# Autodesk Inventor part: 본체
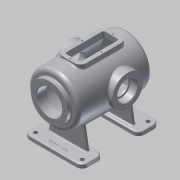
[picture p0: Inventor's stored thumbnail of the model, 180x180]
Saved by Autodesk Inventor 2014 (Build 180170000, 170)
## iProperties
Created: 2016-02
Part Number: 본체
Material: 알루미늄 6061
Document SubType Name: Modeling
Designer: mduedu
Density: 2.71 g/cm^3
Appearance: 알루미늄 - 평지
Mass: 3305.63 g
Surface Area: 2487.05 cm^2
Volume: 1219.79 cm^3
Author: mduedu
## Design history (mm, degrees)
sketch "스케치2"
  geometry: L1 (0, 100)-(0, -100); L2 (65, -87.083)-(65, 100); L3 (65, 100)-(0, 100); A1 r 170 centre (0, 70) between (0, -100) and (65, -87.083); 2 further points
  constraints: 6 end point, 2 point on circle, 1 centre point, 1 coincident, 1 horizontal, 1 midpoint, 1 parallel, 1 point on line, 1 vertical
  dimensions: "d3" = 200 distance of L1.start L1.end; "d5" = 130 diameter of L2 L1; "d6" = 170 radius of A1
revolve "회전1" sketch "스케치2" stored, may be unused: angle "d7" = 90 deg
sketch "스케치3"
  geometry: C1 r 47.5 at (0, 0); 1 further point
  constraints: 1 centre point, 1 coincident
  dimensions: "d8" = 95 diameter of C1
extrude "돌출2" join sketch "스케치3" distance "d10" = 10; taper "d11" = 0 deg
sketch "스케치5"
  geometry: L1 (47.5, 110)-(47.5, 100) reference; L2 (47.5, 100)-(65, 100) reference; L3 (65, 100)-(65, -87.083) reference; L4 (-65, -87.083)-(-65, 100) reference; L5 (-65, 100)-(-47.5, 100) reference; L6 (-47.5, 100)-(-47.5, 110) reference; L7 (-47.5, 110)-(47.5, 110) reference; L8 (55, 85)-(55, -80.25); L9 (0, 85)-(55, 85); L10 (0, 85)-(0, -90); A1 r 170 centre (0, 70) between (-65, -87.083) and (0, -100) reference; A2 r 170 centre (0, 70) between (0, -100) and (65, -87.083) reference; A3 r 160 centre (0, 70) between (0, -90) and (55, -80.25); 1 further point
  constraints: 6 end point, 2 point on circle, 1 centre point, 1 parallel, 1 perpendicular, 1 point on line, 1 vertical
  dimensions: "d13" = 10 distance between parallel lines of L3 L8; "d14" = 10 radial gap between concentric circles of A3 A1; "d15" = 15 distance between parallel lines of L9 L2
revolve "회전2" sketch "스케치5" stored, may be unused: angle "d16" = 90 deg
hole "구멍1" diameter "d19" = 65; stored, may be unused: countersink angle "d23" = 90 deg, drill point angle "d25" = 118 deg; dims "d17" = 10, "d18" = 10, "d20" = 6, "d21" = 4, "d22" = 2, "d24" = 8
node "작업 평면1"
sketch "스케치6"
  geometry: L1 (47.5, 110)-(-47.5, 110) reference; C1 r 40 at (0, -17); 1 further point
  constraints: 1 centre point, 1 vertical alignment
  dimensions: "d27" = 80 diameter of C1; "d29" = 127 distance from line of C1.centre L1
extrude "돌출3" join sketch "스케치6" stored distance "d30" = 10; taper "d31" = 0 deg
hole "구멍2" diameter "d34" = 42; stored, may be unused: countersink angle "d38" = 90 deg, drill point angle "d40" = 118 deg; dims "d32" = 10, "d33" = 10, "d35" = 6, "d36" = 52, "d37" = 18, "d39" = 8
sketch "스케치7" dims "d41" = 65
  geometry: C1 r 40 at (0, 0) reference; 3 further points
  constraints: 2 vertical alignment, 1 coincident, 2 other
hole "구멍3" sketch "스케치7" at (0, 32.5) diameter "d43" = 3.242; stored, may be unused: countersink angle "d47" = 90 deg, drill point angle "d49" = 118 deg; dims "d44" = 11, "d45" = 13, "d46" = 18, "d48" = 13
sketch "스케치8" dims "d53" = 80
  geometry: 3 further points
  constraints: 2 vertical alignment, 1 coincident, 2 other
hole "구멍4" sketch "스케치8" at (0, 40) diameter "d56" = 3.242; stored, may be unused: countersink angle "d60" = 90 deg, drill point angle "d62" = 118 deg; dims "d57" = 11, "d58" = 13, "d59" = 18, "d61" = 13
fillet "모깎기1" dims "d66" = 10
fillet "모깎기2" dims "d67" = 3
fillet "모깎기3" dims "d68" = 0.3
chamfer "모따기1" distance "d69" = 1; stored, may be unused: second distance "d70" = 2, angle "d71" = 45 deg
node "작업 평면2"
sketch "스케치9"
  geometry: L1 (75, 100)-(-75, 100); L2 (-75, 100)-(-75, -100); L3 (-75, -100)-(75, -100); L4 (75, -100)-(75, 100); 1 further point
  constraints: 8 end point, 2 parallel, 1 horizontal, 1 perpendicular
  dimensions: "d73" = 200 distance of L3.end L1.start; "d75" = 150 distance of L2.end L3.end; "d76" = 100 distance from line of L1 point (0, 0); "d77" = 75 distance from line of L4 point (0, 0)
extrude "돌출4" join sketch "스케치9" distance "d78" = 10; taper "d79" = 0 deg
sketch "스케치10"
  geometry: L1 (-75, -100)-(75, -100) reference; L2 (75, 100)-(-75, 100) reference; L3 (0, -100)-(0, 100); L4 (-75, 100)-(-75, -100) reference; L5 (75, -100)-(75, 100) reference; L6 (-75, 0)-(75, 0); L7 (-50, -63)-(50, -63); L8 (50, -63)-(50, -55); L9 (50, -55)-(-50, -55); L10 (-50, -55)-(-50, -63); L11 (-50, 63)-(50, 63); L12 (50, 63)-(50, 55); L13 (50, 55)-(-50, 55); L14 (-50, 55)-(-50, 63); 1 further point
  constraints: 20 end point, 4 midpoint, 4 symmetric about line, 2 parallel, 1 horizontal, 1 perpendicular, 1 other
  dimensions: "d80" = 8 distance of L9.end L7.start; "d82" = 100 distance of L7.start L7.end; "d83" = 55 distance between parallel lines of L9 L6
extrude "돌출5" join sketch "스케치10" stored distance "d84" = 10; taper "d85" = 0 deg
feature "면 기울기1" dims angle "d86" = 10 deg
sketch "스케치11"
  geometry: L1 (-110, 55)-(-51.482, 55) reference; L2 (-110, -55)-(-51.482, -55) reference; L3 (-95, 55)-(-95, -55); L4 (-65, 90)-(-65, -80.25) reference; 1 further point
  constraints: 2 end point, 2 point on line, 1 perpendicular
  dimensions: "d87" = 30 distance between parallel lines of L3 L4
feature "리브1" sketch "스케치11" dims "d88" = 1, "d89" = 8, "d90" = 0, "d91" = 0, "d92" = 1, "d93" = 1
sketch "스케치12"
  geometry: L1 (-110, 55)-(-51.482, 55) reference; L2 (-110, -55)-(-51.482, -55) reference; L3 (-110, 100)-(-110, -100) reference; L4 (-120, 152)-(-120, -142) reference; L5 (-110, 45)-(-120, 45); L6 (-120, 45)-(-120, -45); L7 (-120, -45)-(-110, -45); L8 (-110, -45)-(-110, 45); 1 further point
  constraints: 8 end point, 2 parallel, 2 point on line, 1 horizontal, 1 perpendicular
  dimensions: "d94" = 10 distance between parallel lines of L7 L2; "d95" = 10 distance between parallel lines of L1 L5
extrude "돌출6" cut sketch "스케치12" stored distance "d96" = 10; taper "d97" = 0 deg
fillet "모깎기4" dims "d98" = 15
sketch "스케치13"
  geometry: C1 r 5 at (-60, -85); C2 r 5 at (60, -85); C3 r 5 at (60, 85); C4 r 5 at (-60, 85); A1 r 15 centre (-60, -85) between (-75, -85) and (-60, -100) reference; A2 r 15 centre (60, -85) between (60, -100) and (75, -85) reference; A3 r 15 centre (60, 85) between (75, 85) and (60, 100) reference; A4 r 15 centre (-60, 85) between (-60, 100) and (-75, 85) reference; 1 further point
  constraints: 4 centre point, 4 coincident, 3 equal radius
  dimensions: "d99" = 10 diameter of C1
extrude "돌출7" cut sketch "스케치13" stored distance "d101" = 10; taper "d102" = 0 deg
fillet "모깎기5" dims "d103" = 3, "d104" = 3
fillet "모깎기6" dims "d105" = 3
sketch "스케치14"
  geometry: L1 (-60, -100)-(60, -100) reference; 2 further points
  constraints: 1 vertical alignment, 1 other
  dimensions: "d106" = 15 distance from line of point (0, -85) L1
feature "엠보싱1" sketch "스케치14" dims "d3" = 200, "d5" = 130, "d6" = 170, "d14" = 10, "d107" = 0.5, "d108" = 0
node "작업 평면3"
sketch "스케치15"
  geometry: L1 (-30, 60)-(30, 60); L2 (30, 60)-(30, -60); L3 (30, -60)-(-30, -60); L4 (-30, -60)-(-30, 60); 2 further points
  constraints: 8 end point, 2 parallel, 1 horizontal, 1 midpoint, 1 perpendicular, 1 vertical alignment
  dimensions: "d110" = 60 distance of L2.end L3.end; "d112" = 60 distance from line of L3 point (0, 0); "d113" = 120 distance of L1.end L2.end
extrude "돌출8" join sketch "스케치15" stored distance "d114" = 10; taper "d115" = 0 deg
fillet "모깎기7" dims "d116" = 15
sketch "스케치16"
  geometry: L1 (-30, -45)-(-30, 45) reference; L2 (-15, 60)-(15, 60) reference; L3 (30, 45)-(30, -45) reference; L4 (15, -60)-(-15, -60) reference; L5 (15, 50)-(-15, 50); L6 (-20, 45)-(-20, -45); L7 (-15, -50)-(15, -50); L8 (20, -45)-(20, 45); A1 r 15 centre (-15, -45) between (-30, -45) and (-15, -60) reference; A2 r 15 centre (-15, 45) between (-15, 60) and (-30, 45) reference; A3 r 15 centre (15, 45) between (30, 45) and (15, 60) reference; A4 r 15 centre (15, -45) between (15, -60) and (30, -45) reference; A5 r 5 centre (-15, 45) between (-15, 50) and (-20, 45); A6 r 5 centre (-15, -45) between (-20, -45) and (-15, -50); A7 r 5 centre (15, -45) between (15, -50) and (20, -45); A8 r 5 centre (15, 45) between (20, 45) and (15, 50); 1 further point
  constraints: 8 end point, 8 point on circle, 4 centre point, 7 other
  dimensions: "d117" = 10 distance between parallel lines of L6 L1
extrude "돌출9" cut sketch "스케치16" stored distance "d118" = 10; taper "d119" = 0 deg
fillet "모깎기8" dims "d120" = 3
sketch "스케치17"
  geometry: L1 (-30, -45)-(-30, 45) reference; L2 (-15, 60)-(15, 60) reference; L3 (30, 45)-(30, -45) reference; L4 (15, -60)-(-15, -60) reference; L5 (20, -45)-(20, 45) reference; L6 (15, 50)-(-15, 50) reference; L7 (-20, 45)-(-20, -45) reference; L8 (-15, -50)-(15, -50) reference; L9 (15, 55)-(-15, 55); L10 (-25, 45)-(-25, -45); L11 (-15, -55)-(15, -55); L12 (25, -45)-(25, 45); A1 r 15 centre (-15, 45) between (-15, 60) and (-30, 45) reference; A2 r 15 centre (15, 45) between (30, 45) and (15, 60) reference; A3 r 15 centre (15, -45) between (15, -60) and (30, -45) reference; A4 r 15 centre (-15, -45) between (-30, -45) and (-15, -60) reference; A5 r 5 centre (15, -45) between (15, -50) and (20, -45) reference; A6 r 5 centre (15, 45) between (20, 45) and (15, 50) reference; A7 r 5 centre (-15, 45) between (-15, 50) and (-20, 45) reference; A8 r 5 centre (-15, -45) between (-20, -45) and (-15, -50) reference; A9 r 10 centre (-15, 45) between (-15, 55) and (-25, 45); A10 r 10 centre (-15, -45) between (-25, -45) and (-15, -55); A11 r 10 centre (15, -45) between (15, -55) and (25, -45); A12 r 10 centre (15, 45) between (25, 45) and (15, 55); 5 further points
  constraints: 8 end point, 8 point on circle, 4 centre point, 4 midpoint, 7 other
  dimensions: "d121" = 5 distance between parallel lines of L10 L1
hole "구멍5" sketch "스케치17" at (0, 55), (25, 0), (0, -55), (-25, 0) diameter "d122" = 3.242; stored, may be unused: countersink angle "d126" = 90 deg, drill point angle "d128" = 118 deg; dims "d123" = 9, "d124" = 13, "d125" = 18, "d127" = 11
fillet "모깎기9" dims "d129" = 3
node "솔리드2"
pattern_circular "원형 패턴1" dims angle "d51" = 360 deg
mirror "대칭1"
pattern_circular "원형 패턴2" dims angle "d64" = 360 deg
node "절단 모서리 투영1"
node "절단 모서리 투영2"
node "절단 모서리 투영3"
other parameters: "d26" = 75
